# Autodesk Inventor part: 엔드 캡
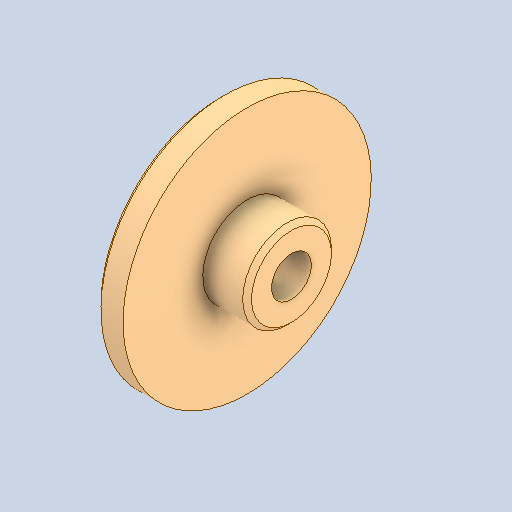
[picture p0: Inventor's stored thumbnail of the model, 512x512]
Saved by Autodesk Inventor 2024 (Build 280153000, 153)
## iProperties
Created: 2025-11
Part Number: 엔드 캡
Material: 강철, 연강
Document SubType Name: Modeling
Designer: Edu07
Density: 7.85 g/cm^3
Appearance: 기본값
Author: jhkim
Sending System: Autodesk Inventor 2026
Preprocessor: ST-DEVELOPER v20.1
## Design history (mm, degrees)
node "엔드 캡1"
node "솔리드2"
node "솔리드1"
